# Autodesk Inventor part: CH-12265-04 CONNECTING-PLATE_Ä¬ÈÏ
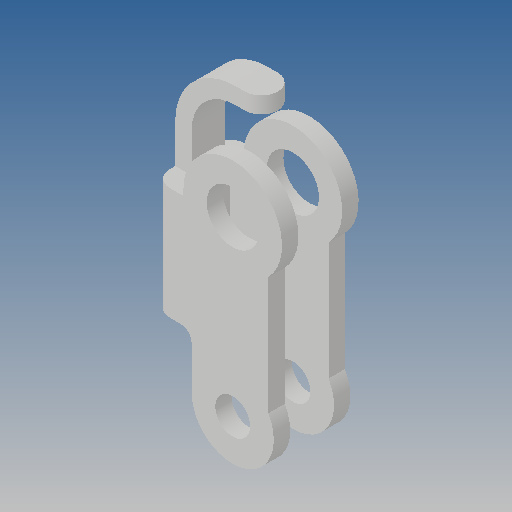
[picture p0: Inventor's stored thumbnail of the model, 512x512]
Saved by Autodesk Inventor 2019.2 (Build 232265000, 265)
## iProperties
Created: 2012-09
Part Number: CH-12265-04 CONNECTING-PLATE_Ä¬ÈÏ
Material: Ogólny
Document SubType Name: Modeling
Designer: CADENGINEERING4
Density: 1 g/cm^3
Appearance: Domyślna
Author: CADENGINEERING4
Revision Number: ÈÎºÎ
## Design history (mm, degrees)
feature "NONE"
node "Bryła1"
